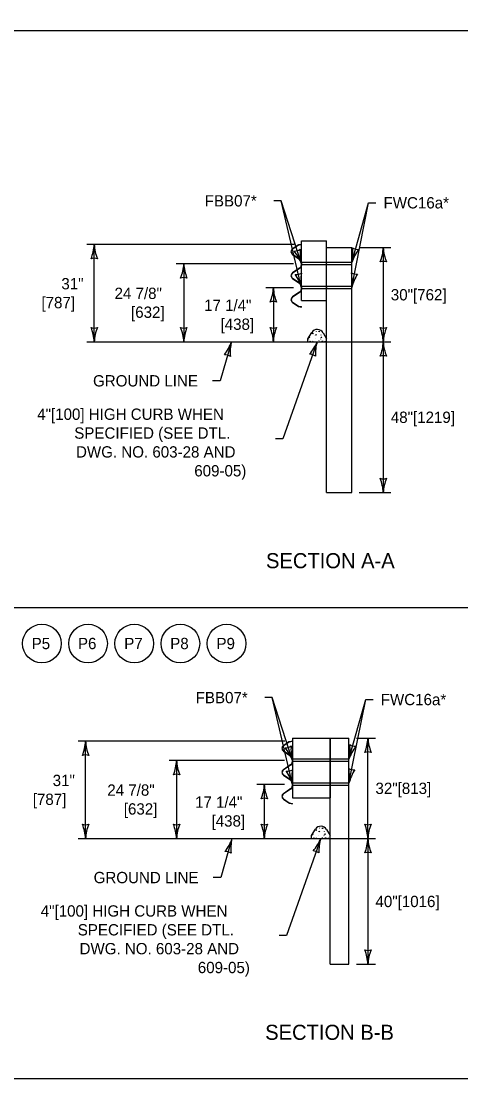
# Model space of a CAD drawing. Extents: x 49991 to 50160, y 49948 to 50051.
# Drawn here: x 50003.54 to 50005.88, y 49987.8 to 49993.41 of the extents above; entities that cross this region are included whole.
import ezdxf

# ---------------------------------------------------------------- set-up
doc = ezdxf.new("R2010")
doc.units = 0
for name, color, linetype in [('Default', 7, 'Continuous'), ('Level 1', 7, 'Continuous'), ('Level 2', 7, 'Continuous'), ('Level 3', 7, 'Continuous'), ('Level 4', 7, 'Continuous')]:
    doc.layers.add(name, color=color, linetype=linetype)

msp = doc.modelspace()

# ---------------------------------------------------------------- linework, layer by layer
at = {"layer": 'Default'}
for p, q in [((50005.0342, 49992.1324), (50005.0342, 49992.114)), ((50005.0342, 49992.0051), (50005.0342, 49991.9867))]:
    msp.add_line(p, q, dxfattribs=at)
at = {"layer": 'Level 1'}
for p, q in [((50005.0342, 49992.2256), (50005.0183, 49992.2226)), ((50005.0345, 49992.2238), (50005.0186, 49992.2209)), ((50005.0342, 49992.2256), (50005.032, 49992.2234)), ((50005.0342, 49991.9274), (50005.0342, 49992.244)), ((50005.0342, 49992.244), (50005.1675, 49992.244)), ((50005.0345, 49992.2238), (50005.0342, 49992.2256)), ((50005.1675, 49991.9274), (50005.1675, 49992.244)), ((50004.9843, 49992.1757), (50004.9831, 49992.1745)), ((50005.0155, 49992.2215), (50004.9857, 49992.2013)), ((50004.9857, 49992.1723), (50005.0255, 49992.1454)), ((50005.0164, 49992.22), (50004.9866, 49992.1999)), ((50004.9866, 49992.1738), (50005.0265, 49992.1469)), ((50005.1675, 49990.9086), (50005.1675, 49992.2086)), ((50005.1675, 49992.2086), (50005.3008, 49992.2086)), ((50005.3008, 49990.9086), (50005.3008, 49992.2086)), ((50005.0193, 49992.1517), (50005.018, 49992.1505)), ((50005.0324, 49992.1324), (50005.0324, 49992.114)), ((50005.0255, 49992.101), (50004.9857, 49992.074)), ((50005.0265, 49992.0995), (50004.9866, 49992.0726)), ((50004.9857, 49992.045), (50005.0255, 49992.0181)), ((50004.9866, 49992.0465), (50005.0265, 49992.0196)), ((50005.0137, 49992.0282), (50005.0124, 49992.027)), ((50005.0324, 49992.0051), (50005.0324, 49991.9867)), ((50005.0255, 49991.9737), (50004.9857, 49991.9467)), ((50005.0265, 49991.9722), (50004.9866, 49991.9453)), ((50005.0023, 49991.958), (50004.9958, 49991.9515)), ((50005.0342, 49991.9898), (50005.0324, 49991.9881)), ((50004.9801, 49991.9358), (50004.978, 49991.9337)), ((50004.9857, 49991.9177), (50005.0155, 49991.8976)), ((50004.9866, 49991.9192), (50005.0164, 49991.8991)), ((50005.0183, 49991.8965), (50005.0342, 49991.8935)), ((50005.0186, 49991.8982), (50005.0345, 49991.8953)), ((50005.0342, 49991.9274), (50005.1675, 49991.9274)), ((50005.0342, 49991.8935), (50005.0345, 49991.8953)), ((50005.0675, 49991.7246), (50005.0889, 49991.7586)), ((50005.0675, 49991.7106), (50005.0675, 49991.7246)), ((50005.0707, 49991.7242), (50005.0712, 49991.7234)), ((50005.0712, 49991.7239), (50005.0717, 49991.7231)), ((50005.1059, 49991.7242), (50005.1064, 49991.7254)), ((50005.1118, 49991.765), (50005.1123, 49991.7642)), ((50005.1346, 49991.7242), (50005.1351, 49991.7234)), ((50005.1351, 49991.7239), (50005.1356, 49991.7231)), ((50005.1374, 49991.7452), (50005.1379, 49991.7464)), ((50005.1376, 49991.7312), (50005.1388, 49991.7337)), ((50005.1487, 49991.7569), (50005.1675, 49991.7246)), ((50005.1577, 49991.7397), (50005.1581, 49991.7407)), ((50005.1675, 49991.7086), (50005.1675, 49991.7246)), ((50005.0675, 49991.7106), (50005.1675, 49991.7086)), ((50005.0951, 49991.7113), (50005.0956, 49991.7125)), ((50005.1175, 49991.7096), (50005.1175, 49991.7096)), ((50005.1175, 49991.7096), (50005.1175, 49991.7096)), ((50005.1267, 49991.7143), (50005.1272, 49991.7155)), ((50005.159, 49991.7113), (50005.1595, 49991.7125)), ((50005.1675, 49990.9086), (50005.3008, 49990.9086)), ((49999.3835, 49990.2991), (50008.1103, 49990.2991)), ((50004.9676, 49989.5862), (50004.9378, 49989.5661)), ((50004.9863, 49989.5903), (50004.9704, 49989.5874)), ((50004.9866, 49989.5886), (50004.9707, 49989.5857)), ((50004.9863, 49989.5903), (50004.9841, 49989.5881)), ((50004.9863, 49989.6067), (50005.1863, 49989.6067)), ((50004.9863, 49989.6067), (50004.9863, 49989.29)), ((50004.9866, 49989.5886), (50004.9863, 49989.5903)), ((50005.1863, 49988.4067), (50005.1863, 49989.6067)), ((50005.1863, 49989.6067), (50005.2863, 49989.6067)), ((50005.1863, 49989.6067), (50005.1863, 49989.29)), ((50005.2863, 49988.4067), (50005.2863, 49989.6067)), ((50004.9364, 49989.5405), (50004.9352, 49989.5392)), ((50004.9378, 49989.5371), (50004.9776, 49989.5102)), ((50004.9686, 49989.5848), (50004.9388, 49989.5647)), ((50004.9388, 49989.5386), (50004.9786, 49989.5117)), ((50004.9714, 49989.5165), (50004.9701, 49989.5152)), ((50004.9845, 49989.4972), (50004.9845, 49989.4788)), ((50004.9863, 49989.4972), (50004.9863, 49989.4788)), ((50004.9776, 49989.4657), (50004.9378, 49989.4388)), ((50004.9786, 49989.4643), (50004.9388, 49989.4374)), ((50004.9378, 49989.4098), (50004.9776, 49989.3829)), ((50004.9388, 49989.4113), (50004.9786, 49989.3844)), ((50004.9658, 49989.393), (50004.9645, 49989.3918)), ((50004.9845, 49989.3699), (50004.9845, 49989.3515)), ((50004.9863, 49989.3699), (50004.9863, 49989.3515)), ((50004.9776, 49989.3384), (50004.9378, 49989.3115)), ((50004.9786, 49989.337), (50004.9388, 49989.3101)), ((50004.9544, 49989.3228), (50004.9479, 49989.3163)), ((50004.9863, 49989.3546), (50004.9845, 49989.3529)), ((50004.9378, 49989.2825), (50004.9676, 49989.2624)), ((50004.9388, 49989.284), (50004.9686, 49989.2638)), ((50004.9704, 49989.2612), (50004.9863, 49989.2583)), ((50004.9707, 49989.263), (50004.9866, 49989.26)), ((50004.9863, 49989.29), (50005.1863, 49989.29)), ((50004.9863, 49989.2583), (50004.9866, 49989.26)), ((50005.0863, 49989.0894), (50005.1076, 49989.1233)), ((50005.0863, 49989.0754), (50005.0863, 49989.0894)), ((50005.0894, 49989.089), (50005.09, 49989.0882)), ((50005.09, 49989.0887), (50005.0905, 49989.0879)), ((50005.1247, 49989.089), (50005.1252, 49989.0902)), ((50005.1305, 49989.1298), (50005.1311, 49989.129)), ((50005.1533, 49989.089), (50005.1539, 49989.0882)), ((50005.1539, 49989.0887), (50005.1544, 49989.0879)), ((50005.1561, 49989.1099), (50005.1567, 49989.1111)), ((50005.1564, 49989.0959), (50005.1576, 49989.0984)), ((50005.1675, 49989.1217), (50005.1863, 49989.0894)), ((50005.1764, 49989.1045), (50005.1769, 49989.1055)), ((50005.1863, 49989.0734), (50005.1863, 49989.0894)), ((50005.0863, 49989.0754), (50005.1863, 49989.0734)), ((50005.1139, 49989.076), (50005.1144, 49989.0772)), ((50005.1363, 49989.0744), (50005.1363, 49989.0744)), ((50005.1363, 49989.0744), (50005.1363, 49989.0744)), ((50005.1455, 49989.0791), (50005.146, 49989.0803)), ((50005.1778, 49989.076), (50005.1783, 49989.0772)), ((50005.1863, 49988.4067), (50005.2863, 49988.4067))]:
    msp.add_line(p, q, dxfattribs=at)
msp.add_lwpolyline([(49999.3835, 49998.9992), (50016.7501, 49998.9992), (50016.7501, 49987.7988), (49999.3835, 49987.7988)], close=True, dxfattribs=at)
for points in [[(50006.1377, 49990.2991), (50006.1377, 49993.358), (49999.3835, 49993.358)], [(50005.0737, 49991.7312), (50005.0753, 49991.7345), (50005.078, 49991.7325), (50005.0737, 49991.7312)], [(50005.0911, 49991.752), (50005.0927, 49991.7554), (50005.0954, 49991.7534), (50005.0911, 49991.752)], [(50005.1091, 49991.7439), (50005.1097, 49991.7477), (50005.1134, 49991.7439)], [(50005.1258, 49991.7616), (50005.1274, 49991.7649), (50005.13, 49991.7629), (50005.1258, 49991.7616)], [(50005.1403, 49991.7337), (50005.1419, 49991.7325), (50005.1376, 49991.7312)], [(50005.0785, 49991.7104), (50005.0807, 49991.7145), (50005.0825, 49991.7103)], [(50005.1417, 49991.7091), (50005.1446, 49991.7145), (50005.147, 49991.709)], [(50005.0925, 49989.0959), (50005.0941, 49989.0993), (50005.0968, 49989.0973), (50005.0925, 49989.0959)], [(50005.1099, 49989.1168), (50005.1115, 49989.1201), (50005.1141, 49989.1181), (50005.1099, 49989.1168)], [(50005.1279, 49989.1087), (50005.1284, 49989.1125), (50005.1321, 49989.1087)], [(50005.1445, 49989.1263), (50005.1461, 49989.1297), (50005.1488, 49989.1277), (50005.1445, 49989.1263)], [(50005.1591, 49989.0984), (50005.1607, 49989.0973), (50005.1564, 49989.0959)], [(50005.0973, 49989.0752), (50005.0994, 49989.0792), (50005.1013, 49989.0751)], [(50005.1605, 49989.0739), (50005.1633, 49989.0792), (50005.1658, 49989.0738)]]:
    msp.add_lwpolyline(points, dxfattribs=at)
for centre, radius, start, end in [((50004.9955, 49992.1868), 0.0175, 124.048, 235.952), ((50004.9955, 49992.1868), 0.0157, 124.048, 235.952), ((50005.0196, 49992.2153), 0.00744, 100.4285, 124.048), ((50005.0196, 49992.2153), 0.00569, 100.4285, 124.048), ((50005.0167, 49992.1324), 0.0157, 0, 55.952), ((50005.0167, 49992.114), 0.0157, 304.048, 0), ((50005.0167, 49992.1324), 0.0175, 0, 55.952), ((50005.0167, 49992.114), 0.0175, 304.048, 0), ((50004.9955, 49992.0595), 0.0175, 124.048, 235.952), ((50004.9955, 49992.0595), 0.0157, 124.048, 235.952), ((50005.0167, 49992.0051), 0.0157, 0, 55.952), ((50005.0167, 49992.0051), 0.0175, 0, 55.952), ((50004.9955, 49991.9322), 0.0175, 124.048, 235.952), ((50004.9955, 49991.9322), 0.0157, 124.048, 235.952), ((50005.0167, 49991.9867), 0.0157, 304.048, 0), ((50005.0167, 49991.9867), 0.0175, 304.048, 0), ((50005.0196, 49991.9038), 0.00744, 235.952, 259.5715), ((50005.0196, 49991.9038), 0.00569, 235.952, 259.5715), ((50005.1183, 49991.7392), 0.0352, 30.1855, 146.6195), ((50004.9717, 49989.5801), 0.00744, 100.4285, 124.048), ((50004.9717, 49989.5801), 0.00569, 100.4285, 124.048), ((50004.9476, 49989.5516), 0.0175, 124.048, 235.952), ((50004.9476, 49989.5516), 0.0157, 124.048, 235.952), ((50004.9688, 49989.4972), 0.0157, 0, 55.952), ((50004.9688, 49989.4788), 0.0157, 304.048, 0), ((50004.9688, 49989.4972), 0.0175, 0, 55.952), ((50004.9688, 49989.4788), 0.0175, 304.048, 0), ((50004.9476, 49989.4243), 0.0175, 124.048, 235.952), ((50004.9476, 49989.4243), 0.0157, 124.048, 235.952), ((50004.9688, 49989.3699), 0.0157, 0, 55.952), ((50004.9688, 49989.3699), 0.0175, 0, 55.952), ((50004.9476, 49989.297), 0.0175, 124.048, 235.952), ((50004.9476, 49989.297), 0.0157, 124.048, 235.952), ((50004.9688, 49989.3515), 0.0157, 304.048, 0), ((50004.9688, 49989.3515), 0.0175, 304.048, 0), ((50004.9717, 49989.2685), 0.00744, 235.952, 259.5715), ((50004.9717, 49989.2685), 0.00569, 235.952, 259.5715), ((50005.137, 49989.104), 0.0352, 30.1855, 146.6195)]:
    msp.add_arc(centre, radius, start, end, dxfattribs=at)
at = {"layer": 'Level 2'}
for centre in [(50003.6549, 49990.1082), (50003.9002, 49990.1082), (50004.1455, 49990.1082), (50004.3908, 49990.1082), (50004.6361, 49990.1082)]:
    msp.add_circle(centre, 0.1026, dxfattribs=at)
at = {"layer": 'Level 3'}
for p, q in [((50004.9263, 49992.4568), (50004.8863, 49992.4568)), ((50005.0342, 49992.1228), (50004.9263, 49992.4568)), ((50005.0342, 49991.9959), (50004.9263, 49992.4568)), ((50005.3008, 49992.1294), (50005.3897, 49992.4463)), ((50005.3008, 49991.997), (50005.3897, 49992.4463)), ((50005.3897, 49992.4463), (50005.4297, 49992.4463)), ((50004.9942, 49992.2256), (50003.893, 49992.2256)), ((50003.933, 49991.7086), (50003.933, 49992.2256)), ((50005.3408, 49992.2086), (50005.5085, 49992.2086)), ((50005.4685, 49992.2086), (50005.4685, 49991.7086)), ((50004.9924, 49992.1232), (50004.3689, 49992.1232)), ((50004.4089, 49992.1232), (50004.4089, 49991.7086)), ((50005.1675, 49992.1232), (50005.1675, 49992.1294)), ((50005.1675, 49992.1232), (50005.1675, 49992.1169)), ((50005.1675, 49991.9961), (50005.1675, 49992.0024)), ((50004.9924, 49991.9959), (50004.8444, 49991.9959)), ((50004.8844, 49991.9959), (50004.8844, 49991.7086)), ((50005.1675, 49991.9961), (50005.1675, 49991.9898)), ((50003.893, 49991.7086), (50005.5085, 49991.7086)), ((50004.6615, 49991.7086), (50004.6018, 49991.5019)), ((50005.1175, 49991.7096), (50004.9357, 49991.1948)), ((50005.4685, 49991.7086), (50005.4685, 49990.9086)), ((50004.6018, 49991.5019), (50004.5618, 49991.5019)), ((50004.9357, 49991.1948), (50004.8957, 49991.1948)), ((50005.3408, 49990.9086), (50005.5085, 49990.9086)), ((50004.8784, 49989.8213), (50004.8384, 49989.8213)), ((50004.9863, 49989.4874), (50004.8784, 49989.8213)), ((50004.9863, 49989.3611), (50004.8784, 49989.8213)), ((50005.2863, 49989.4942), (50005.3751, 49989.8111)), ((50005.2863, 49989.3671), (50005.3751, 49989.8111)), ((50005.3751, 49989.8111), (50005.4151, 49989.8111)), ((50004.9463, 49989.5903), (50003.8469, 49989.5903)), ((50003.8869, 49989.0734), (50003.8869, 49989.5903)), ((50005.3263, 49989.6067), (50005.4269, 49989.6067)), ((50005.3869, 49989.0734), (50005.3869, 49989.6067)), ((50004.9445, 49989.488), (50004.3304, 49989.488)), ((50004.3704, 49989.488), (50004.3704, 49989.0734)), ((50004.9445, 49989.3607), (50004.7965, 49989.3607)), ((50004.8365, 49989.3607), (50004.8365, 49989.0734)), ((50003.8469, 49989.0734), (50005.4269, 49989.0734)), ((50004.6648, 49989.0734), (50004.6051, 49988.8667)), ((50005.1363, 49989.0744), (50004.9545, 49988.5595)), ((50005.3869, 49989.0734), (50005.3869, 49988.4067)), ((50004.6051, 49988.8667), (50004.5651, 49988.8667)), ((50004.9545, 49988.5595), (50004.9145, 49988.5595)), ((50005.3263, 49988.4067), (50005.4269, 49988.4067))]:
    msp.add_line(p, q, dxfattribs=at)
for centre, radius, start, end in [((50003.7109, 49992.2347), 0.2223, 337.456, 357.6395), ((50004.1657, 49992.237), 0.233, 182.8273, 202.0772), ((50004.9948, 49992.2448), 0.0548, 270.0345, 305.7569), ((50004.8163, 49992.0404), 0.233, 20.723, 39.9729), ((50005.2484, 49992.1823), 0.2223, 175.3517, 195.5352), ((50005.0737, 49992.1812), 0.233, 347.164, 6.4139), ((50005.5123, 49992.0607), 0.2223, 141.7927, 161.9762), ((50005.3355, 49992.2529), 0.0548, 236.4755, 272.1979), ((50005.2464, 49992.2178), 0.2223, 337.456, 357.6395), ((50005.7012, 49992.2201), 0.233, 182.8273, 202.0772), ((50003.933, 49992.0973), 0.0548, 72.1388, 107.8612), ((50004.1868, 49992.1323), 0.2223, 337.456, 357.6395), ((50004.6416, 49992.1347), 0.233, 182.8273, 202.0772), ((50005.4685, 49992.0804), 0.0548, 72.1388, 107.8612), ((50005.005, 49992.1207), 0.0548, 265.3085, 301.0309), ((50004.8102, 49991.9317), 0.233, 15.997, 35.2468), ((50005.2526, 49992.0376), 0.2223, 170.6257, 190.8092), ((50005.3257, 49992.1228), 0.0548, 240.9535, 276.6758), ((50005.0703, 49992.0309), 0.233, 351.6419, 10.8918), ((50005.517, 49991.9449), 0.2223, 146.2706, 166.4542), ((50004.4089, 49991.995), 0.0548, 72.1388, 107.8612), ((50004.6623, 49992.005), 0.2223, 337.456, 357.6395), ((50005.1171, 49992.0074), 0.233, 182.8273, 202.0772), ((50004.8844, 49991.8677), 0.0548, 72.1388, 107.8612), ((50003.933, 49991.8368), 0.0548, 252.1388, 287.8612), ((50003.7003, 49991.6971), 0.233, 2.8273, 22.0772), ((50004.1552, 49991.6994), 0.2223, 157.456, 177.6395), ((50004.4089, 49991.8368), 0.0548, 252.1388, 287.8612), ((50004.1762, 49991.6971), 0.233, 2.8273, 22.0772), ((50004.631, 49991.6994), 0.2223, 157.456, 177.6395), ((50004.8844, 49991.8368), 0.0548, 252.1388, 287.8612), ((50004.6517, 49991.6971), 0.233, 2.8273, 22.0772), ((50005.1066, 49991.6994), 0.2223, 157.456, 177.6395), ((50005.4685, 49991.8368), 0.0548, 252.1388, 287.8612), ((50005.2358, 49991.6971), 0.233, 2.8273, 22.0772), ((50005.6907, 49991.6994), 0.2223, 157.456, 177.6395), ((50004.4507, 49991.7791), 0.2223, 321.3407, 341.5242), ((50004.8883, 49991.6551), 0.233, 166.712, 185.9619), ((50004.9111, 49991.7922), 0.2223, 318.0037, 338.1872), ((50005.3408, 49991.6429), 0.233, 163.375, 182.6248), ((50005.2464, 49991.7178), 0.2223, 337.456, 357.6395), ((50005.7012, 49991.7201), 0.233, 182.8273, 202.0772), ((50004.626, 49991.5854), 0.0548, 56.0235, 91.7459), ((50005.0748, 49991.5887), 0.0548, 52.6865, 88.4089), ((50005.4685, 49991.5804), 0.0548, 72.1388, 107.8612), ((50005.4685, 49991.0368), 0.0548, 252.1388, 287.8612), ((50005.2358, 49990.8971), 0.233, 2.8273, 22.0772), ((50005.6907, 49990.8994), 0.2223, 157.456, 177.6395), ((50003.6648, 49989.5995), 0.2223, 337.456, 357.6395), ((50004.1196, 49989.6018), 0.233, 182.8273, 202.0772), ((50005.1647, 49989.6159), 0.2223, 337.456, 357.6395), ((50005.6196, 49989.6182), 0.233, 182.8273, 202.0772), ((50004.9469, 49989.6094), 0.0548, 270.0345, 305.7569), ((50004.7684, 49989.4049), 0.233, 20.723, 39.9729), ((50005.2005, 49989.5469), 0.2223, 175.3517, 195.5352), ((50005.0591, 49989.546), 0.233, 347.164, 6.4139), ((50005.4977, 49989.4254), 0.2223, 141.7927, 161.9762), ((50005.3209, 49989.6177), 0.0548, 236.4755, 272.1979), ((50005.3869, 49989.4785), 0.0548, 72.1388, 107.8612), ((50003.8869, 49989.4621), 0.0548, 72.1388, 107.8612), ((50004.1483, 49989.4971), 0.2223, 337.456, 357.6395), ((50004.6031, 49989.4995), 0.233, 182.8273, 202.0772), ((50004.9571, 49989.4859), 0.0548, 265.2961, 301.0185), ((50004.7623, 49989.2969), 0.233, 15.9846, 35.2345), ((50005.2047, 49989.4027), 0.2223, 170.6133, 190.7968), ((50005.3114, 49989.4929), 0.0548, 240.8222, 276.5446), ((50005.0558, 49989.4015), 0.233, 351.5107, 10.7606), ((50005.5023, 49989.3146), 0.2223, 146.1394, 166.3229), ((50004.3704, 49989.3597), 0.0548, 72.1388, 107.8612), ((50004.6144, 49989.3698), 0.2223, 337.456, 357.6395), ((50005.0692, 49989.3722), 0.233, 182.8273, 202.0772), ((50004.8365, 49989.2325), 0.0548, 72.1388, 107.8612), ((50003.8869, 49989.2016), 0.0548, 252.1388, 287.8612), ((50003.6542, 49989.0619), 0.233, 2.8273, 22.0772), ((50004.1091, 49989.0642), 0.2223, 157.456, 177.6395), ((50004.3704, 49989.2016), 0.0548, 252.1388, 287.8612), ((50004.1377, 49989.0619), 0.233, 2.8273, 22.0772), ((50004.5925, 49989.0642), 0.2223, 157.456, 177.6395), ((50004.8365, 49989.2016), 0.0548, 252.1388, 287.8612), ((50004.6038, 49989.0619), 0.233, 2.8273, 22.0772), ((50005.0587, 49989.0642), 0.2223, 157.456, 177.6395), ((50005.3869, 49989.2016), 0.0548, 252.1388, 287.8612), ((50005.1542, 49989.0619), 0.233, 2.8273, 22.0772), ((50005.609, 49989.0642), 0.2223, 157.456, 177.6395), ((50004.454, 49989.1438), 0.2223, 321.3407, 341.5242), ((50004.8916, 49989.0198), 0.233, 166.712, 185.9619), ((50004.9299, 49989.157), 0.2223, 318.0037, 338.1872), ((50005.3596, 49989.0077), 0.233, 163.375, 182.6248), ((50005.1647, 49989.0825), 0.2223, 337.456, 357.6395), ((50005.6196, 49989.0849), 0.233, 182.8273, 202.0772), ((50004.6293, 49988.9502), 0.0548, 56.0235, 91.7459), ((50005.0936, 49988.9535), 0.0548, 52.6865, 88.4089), ((50005.3869, 49988.9452), 0.0548, 72.1388, 107.8612), ((50005.3869, 49988.5349), 0.0548, 252.1388, 287.8612), ((50005.1542, 49988.3952), 0.233, 2.8273, 22.0772), ((50005.609, 49988.3976), 0.2223, 157.456, 177.6395)]:
    msp.add_arc(centre, radius, start, end, dxfattribs=at)
at = {"layer": 'Level 4'}
for p, q in [((50005.3008, 49992.1294), (50005.0342, 49992.1294)), ((50005.3008, 49992.1169), (50005.0342, 49992.1169)), ((50005.3008, 49992.0024), (50005.0342, 49992.0024)), ((50005.3008, 49991.9898), (50005.0342, 49991.9898)), ((50005.2863, 49989.4942), (50004.9863, 49989.4942)), ((50005.2863, 49989.4817), (50004.9863, 49989.4817)), ((50005.2863, 49989.3671), (50004.9863, 49989.3671)), ((50005.2863, 49989.3546), (50004.9863, 49989.3546))]:
    msp.add_line(p, q, dxfattribs=at)

# ---------------------------------------------------------------- texts
at = {"layer": 'Level 2'}
for s, height, p in [('FBB07*', 0.06, (50004.5199, 49992.4268)), ('FWC16a*', 0.06, (50005.4697, 49992.4163)), ('31"', 0.06, (50003.7585, 49991.9871)), ('24 7/8"', 0.06, (50004.0409, 49991.9359)), ('[787]', 0.06, (50003.6526, 49991.8871)), ('30"[762]', 0.06, (50005.5085, 49991.9286)), ('[632]', 0.06, (50004.1285, 49991.8359)), ('17 1/4"', 0.06, (50004.5164, 49991.8722)), ('[438]', 0.06, (50004.604, 49991.7722)), ('GROUND LINE', 0.06, (50003.9267, 49991.4719)), ('4"[100] HIGH CURB WHEN ', 0.06, (50003.6302, 49991.2948)), ('48"[1219]', 0.06, (50005.5085, 49991.2786)), ('SPECIFIED (SEE DTL. ', 0.06, (50003.8269, 49991.1948)), ('DWG. NO. 603-28 AND ', 0.06, (50003.8363, 49991.0948)), ('609-05) ', 0.06, (50004.4645, 49990.9948)), ('SECTION A-A', 0.08, (50004.8455, 49990.5077)), ('P5', 0.06, (50003.6007, 49990.0783)), ('P6', 0.06, (50003.8466, 49990.0784)), ('P7', 0.06, (50004.0925, 49990.0784)), ('P8', 0.06, (50004.3366, 49990.0783)), ('P9', 0.06, (50004.5823, 49990.0783)), ('FBB07*', 0.06, (50004.472, 49989.7913)), ('FWC16a*', 0.06, (50005.4551, 49989.7811)), ('31"', 0.06, (50003.7124, 49989.3519)), ('24 7/8"', 0.06, (50004.0024, 49989.3007)), ('32"[813]', 0.06, (50005.4269, 49989.31)), ('[787]', 0.06, (50003.6065, 49989.2519)), ('[632]', 0.06, (50004.09, 49989.2007)), ('17 1/4"', 0.06, (50004.4685, 49989.237)), ('[438]', 0.06, (50004.5561, 49989.137)), ('GROUND LINE', 0.06, (50003.9299, 49988.8367)), ('40"[1016]', 0.06, (50005.4269, 49988.71)), ('4"[100] HIGH CURB WHEN ', 0.06, (50003.649, 49988.6595)), ('SPECIFIED (SEE DTL. ', 0.06, (50003.8456, 49988.5595)), ('DWG. NO. 603-28 AND ', 0.06, (50003.8551, 49988.4595)), ('609-05) ', 0.06, (50004.4833, 49988.3595)), ('SECTION B-B', 0.08, (50004.8412, 49988.0058))]:
    msp.add_text(s, height=height, dxfattribs=at).set_placement(p)

doc.saveas('drawing.dxf')
